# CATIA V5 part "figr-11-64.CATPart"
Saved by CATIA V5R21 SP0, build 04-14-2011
Part number: Part1
Bounding box of the stored display mesh (mm): x -54 to 54, y -91.936 to 93.838, z -12.649 to 110.643
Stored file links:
  D:\CATIA V5R21 E-RESOURCES\CATIA-V5R21\catia-v5r21-prt\c11-catia-v5r21-prt\c11-catia-v5r21-figr-11-64.CATPart
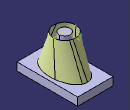
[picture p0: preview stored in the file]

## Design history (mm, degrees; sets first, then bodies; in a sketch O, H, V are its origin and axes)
Set1
  Loft1: Sections (Sketch4; Sketch3)
Body1 (main body)
  Sketch1 on yz-plane, origin (0, 0, 0), H (0, 1, 0), V (0, 0, 1)
    point P1 (93.8379, 11.643)
    line L1 (93.8379, 11.643) -> (93.8379, -12.6487)
    line L2 (93.8379, -12.6487) -> (-91.9362, -12.6487)
    line L3 (-91.9362, -12.6487) -> (-91.9362, 11.643)
    line L4 (-91.9362, 11.643) -> (93.8379, 11.643)
    point P5 (93.8379, 11.643)
    vertical: L1 V, L3 V
    horizontal: L2 H, L4 H
    coincidence: P5 P1
  Pad1: profile Sketch1, direction (1, 0, 0), length 54, mirrored extent
  Sketch2 on face of Pad1, origin (0, 0, 11.643), H (1, 0, 0), V (0, 1, 0)
    circle A1 centre (0, 0) radius 16.7533
    point P1 (16.7533, 0)
    coincidence: A1 P1, P1 H
  Pad2: profile Sketch2, direction (0, 0, 1), length 99
  Sketch3 on face of Pad2, origin (0, 0, 110.643), H (1, 0, 0), V (0, 1, 0)
    point P1 (0, 42.8937)
    point P2 (33.9651, 0)
    projected circle E1 centre (0, 0) radius 16.7533 from edge [face of Pad2 | face of Pad2]
    circle A1 centre (0, 0) radius 33.9651
    point P3 (0, 33.9651)
    coincidence: P1 V, P2 H, A1 P2, A1 P3, P3 V
  Sketch4 on face of Pad1, origin (0, 0, 11.643), H (1, 0, 0), V (0, 1, 0)
    ellipse A1 centre (0, 0) semi-axes 69.9141, 43.1918 rotation 90
    point P1 (0, 69.9141)
    point P2 (43.1918, 0)
    coincidence: P1 V, P2 H, A1 P1, A1 P2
